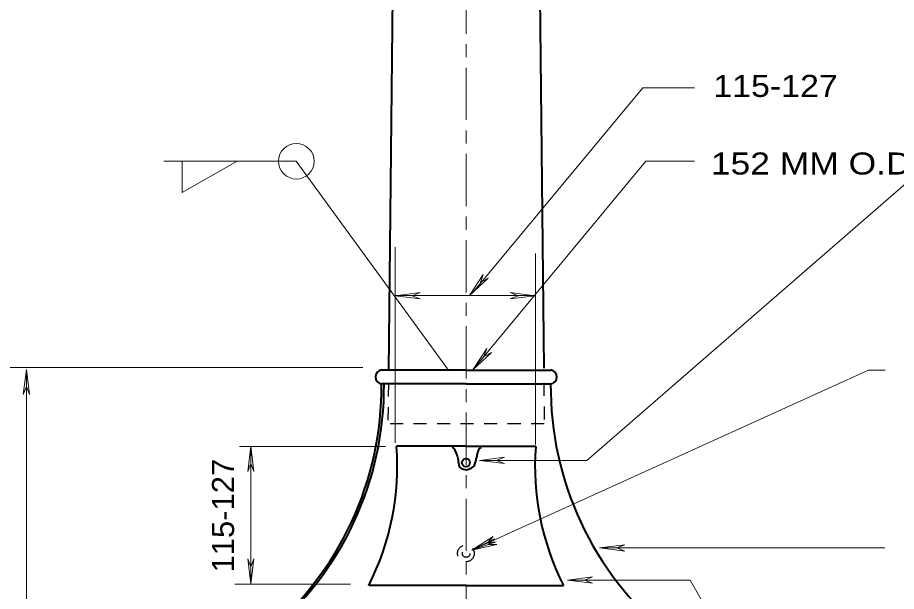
# Model space of a CAD drawing. Extents: x 312583 to 312854, y 144419 to 144597.
# Drawn here: x 312624.63 to 312654.89, y 144455.33 to 144475.1 of the extents above; entities that cross this region are included whole.
import ezdxf

# ---------------------------------------------------------------- set-up
doc = ezdxf.new("R2010")
doc.units = 0
doc.header["$LTSCALE"] = 0.3
doc.linetypes.add('LONG_DASH_SHORT_DASH', pattern=[9.9, 6, -1.2, 1.5, -1.2])
doc.linetypes.add('SHORT_DASHED', pattern=[2.7, 1.5, -1.2])
doc.layers.add('1', color=7, linetype='Continuous', lineweight=40)
doc.layers.add('2', color=7, linetype='Continuous', lineweight=13)

msp = doc.modelspace()

# ---------------------------------------------------------------- linework, layer by layer
at = {"layer": '1', "linetype": 'LONG_DASH_SHORT_DASH', "lineweight": 13}
msp.add_line((312640.0738, 144435.9326), (312640.0738, 144549.4913), dxfattribs=at)
at = {"layer": '1'}
for p, q in [((312638.2185, 144543.4576), (312637.4058, 144462.9576)), ((312641.9292, 144543.4576), (312642.7495, 144463.0189)), ((312640.0738, 144462.9576), (312637.1605, 144462.9576)), ((312640.0738, 144462.9576), (312637.1605, 144462.9576)), ((312640.0738, 144462.9576), (312637.1605, 144462.9576)), ((312640.0738, 144462.9576), (312637.1605, 144462.9576)), ((312640.0738, 144462.9576), (312637.1605, 144462.9576)), ((312640.0738, 144462.9576), (312637.1605, 144462.9576)), ((312640.0738, 144462.9576), (312637.1605, 144462.9576)), ((312640.0738, 144462.9576), (312637.1605, 144462.9576)), ((312640.0738, 144462.9576), (312642.9872, 144462.9576)), ((312640.0738, 144462.9576), (312642.9872, 144462.9576)), ((312640.0738, 144462.9576), (312642.9872, 144462.9576)), ((312640.0738, 144462.9576), (312642.9872, 144462.9576)), ((312640.0738, 144462.9576), (312642.9872, 144462.9576)), ((312640.0738, 144462.9576), (312642.9872, 144462.9576)), ((312640.0738, 144462.9576), (312642.9872, 144462.9576)), ((312640.0738, 144462.9576), (312642.9872, 144462.9576)), ((312640.0738, 144462.4823), (312637.1605, 144462.4823)), ((312640.0738, 144462.4823), (312637.1605, 144462.4823)), ((312640.0738, 144462.4823), (312637.1605, 144462.4823)), ((312640.0738, 144462.4823), (312637.1605, 144462.4823)), ((312640.0738, 144462.4823), (312637.1605, 144462.4823)), ((312640.0738, 144462.4823), (312637.1605, 144462.4823)), ((312640.0738, 144462.4823), (312637.1605, 144462.4823)), ((312640.0738, 144462.4823), (312637.1605, 144462.4823)), ((312640.0738, 144462.4823), (312642.9872, 144462.4823)), ((312640.0738, 144462.4823), (312642.9872, 144462.4823)), ((312640.0738, 144462.4823), (312642.9872, 144462.4823)), ((312640.0738, 144462.4823), (312642.9872, 144462.4823)), ((312640.0738, 144462.4823), (312642.9872, 144462.4823)), ((312640.0738, 144462.4823), (312642.9872, 144462.4823)), ((312640.0738, 144462.4823), (312642.9872, 144462.4823)), ((312640.0738, 144462.4823), (312642.9872, 144462.4823)), ((312640.0738, 144460.3279), (312637.6818, 144460.3279)), ((312640.0738, 144460.3279), (312637.6818, 144460.3279)), ((312640.0738, 144460.3279), (312637.6818, 144460.3279)), ((312640.0738, 144460.3279), (312637.6818, 144460.3279)), ((312640.0738, 144460.3279), (312637.6818, 144460.3279)), ((312640.0738, 144460.3279), (312637.6818, 144460.3279)), ((312640.0738, 144460.3279), (312637.6818, 144460.3279)), ((312640.0738, 144460.3279), (312637.6818, 144460.3279)), ((312640.0738, 144460.3279), (312642.4735, 144460.3279)), ((312640.0738, 144460.3279), (312642.4735, 144460.3279)), ((312640.0738, 144460.3279), (312642.4735, 144460.3279)), ((312640.0738, 144460.3279), (312642.4735, 144460.3279)), ((312640.0738, 144460.3279), (312642.4735, 144460.3279)), ((312640.0738, 144460.3279), (312642.4735, 144460.3279)), ((312640.0738, 144460.3279), (312642.4735, 144460.3279)), ((312640.0738, 144460.3279), (312642.4735, 144460.3279)), ((312640.0738, 144455.5363), (312636.7235, 144455.5363)), ((312640.0738, 144455.5363), (312636.7235, 144455.5363)), ((312640.0738, 144455.5363), (312636.7235, 144455.5363)), ((312640.0738, 144455.5363), (312636.7235, 144455.5363)), ((312640.0738, 144455.5363), (312636.7235, 144455.5363)), ((312640.0738, 144455.5363), (312636.7235, 144455.5363)), ((312640.0738, 144455.5363), (312636.7235, 144455.5363)), ((312640.0738, 144455.5363), (312636.7235, 144455.5363)), ((312640.0738, 144455.5363), (312643.4318, 144455.5363)), ((312640.0738, 144455.5363), (312643.4318, 144455.5363)), ((312640.0738, 144455.5363), (312643.4318, 144455.5363)), ((312640.0738, 144455.5363), (312643.4318, 144455.5363)), ((312640.0738, 144455.5363), (312643.4318, 144455.5363)), ((312640.0738, 144455.5363), (312643.4318, 144455.5363)), ((312640.0738, 144455.5363), (312643.4318, 144455.5363)), ((312640.0738, 144455.5363), (312643.4318, 144455.5363))]:
    msp.add_line(p, q, dxfattribs=at)
at = {"layer": '1', "linetype": 'SHORT_DASHED', "lineweight": 25}
for p, q in [((312637.3982, 144462.4899), (312637.3828, 144461.1023)), ((312642.7495, 144462.5129), (312642.7648, 144461.1023)), ((312642.7648, 144461.1023), (312637.3828, 144461.1023))]:
    msp.add_line(p, q, dxfattribs=at)
at = {"layer": '1'}
msp.add_circle((312640.0666, 144459.7649), 0.1386, dxfattribs=at)
at = {"layer": '1', "linetype": 'SHORT_DASHED', "lineweight": 25}
for centre, radius in [((312640.0671, 144456.6374), 0.2875), ((312640.0772, 144456.6297), 0.1279)]:
    msp.add_circle(centre, radius, dxfattribs=at)
at = {"layer": '1'}
for centre, radius, start, end in [((312637.1893, 144462.7199), 0.241, 96.16558, 263.83442), ((312637.1893, 144462.7199), 0.241, 96.16558, 263.83442), ((312637.1893, 144462.7199), 0.241, 96.16558, 263.83442), ((312637.1893, 144462.7199), 0.241, 96.16558, 263.83442), ((312637.1893, 144462.7199), 0.241, 96.16558, 263.83442), ((312637.1893, 144462.7199), 0.241, 96.16558, 263.83442), ((312637.1893, 144462.7199), 0.241, 96.16558, 263.83442), ((312637.1893, 144462.7199), 0.241, 96.16558, 263.83442), ((312642.9603, 144462.7199), 0.241, 276.16558, 83.83442), ((312642.9603, 144462.7199), 0.241, 276.16558, 83.83442), ((312642.9603, 144462.7199), 0.241, 276.16558, 83.83442), ((312642.9603, 144462.7199), 0.241, 276.16558, 83.83442), ((312642.9603, 144462.7199), 0.241, 276.16558, 83.83442), ((312642.9603, 144462.7199), 0.241, 276.16558, 83.83442), ((312642.9603, 144462.7199), 0.241, 276.16558, 83.83442), ((312642.9603, 144462.7199), 0.241, 276.16558, 83.83442), ((312626.0861, 144462.3949), 11.0776, 309.56623, 0.44182), ((312626.0861, 144462.3949), 11.0776, 309.56623, 0.44182), ((312626.0861, 144462.3949), 11.0776, 309.56623, 0.44182), ((312626.0861, 144462.3949), 11.0776, 309.56623, 0.44182), ((312626.0861, 144462.3949), 11.0776, 309.56623, 0.44182), ((312626.0861, 144462.3949), 11.0776, 309.56623, 0.44182), ((312626.0861, 144462.3949), 11.0776, 309.56623, 0.44182), ((312626.1714, 144462.3949), 11.0776, 309.56623, 0.44182), ((312654.0635, 144462.3949), 11.0776, 179.55818, 230.43377), ((312654.0635, 144462.3949), 11.0776, 179.55818, 230.43377), ((312654.0635, 144462.3949), 11.0776, 179.55818, 230.43377), ((312654.0635, 144462.3949), 11.0776, 179.55818, 230.43377), ((312654.0635, 144462.3949), 11.0776, 179.55818, 230.43377), ((312654.0635, 144462.3949), 11.0776, 179.55818, 230.43377), ((312654.0635, 144462.3949), 11.0776, 179.55818, 230.43377), ((312654.0635, 144462.3949), 11.0776, 179.55818, 230.43377), ((312628.609, 144459.6464), 9.0952, 333.10708, 4.27306), ((312628.609, 144459.6464), 9.0952, 333.10708, 4.27306), ((312628.609, 144459.6464), 9.0952, 333.10708, 4.27306), ((312628.609, 144459.6464), 9.0952, 333.10708, 4.27306), ((312628.609, 144459.6464), 9.0952, 333.10708, 4.27306), ((312628.609, 144459.6464), 9.0952, 333.10708, 4.27306), ((312628.609, 144459.6464), 9.0952, 333.10708, 4.27306), ((312628.609, 144459.6464), 9.0952, 333.10708, 4.27306), ((312651.5405, 144459.6464), 9.0952, 175.72694, 206.89292), ((312651.5405, 144459.6464), 9.0952, 175.72694, 206.89292), ((312651.5405, 144459.6464), 9.0952, 175.72694, 206.89292), ((312651.5405, 144459.6464), 9.0952, 175.72694, 206.89292), ((312651.5405, 144459.6464), 9.0952, 175.72694, 206.89292), ((312651.5405, 144459.6464), 9.0952, 175.72694, 206.89292), ((312651.5405, 144459.6464), 9.0952, 175.72694, 206.89292), ((312651.5405, 144459.6464), 9.0952, 175.72694, 206.89292)]:
    msp.add_arc(centre, radius, start, end, dxfattribs=at)
msp.add_spline([(312639.5985, 144460.3203), (312639.6752, 144460.2129), (312639.7288, 144460.0826), (312639.7748, 144459.9599), (312639.8055, 144459.8066), (312639.8592, 144459.6073), (312639.9818, 144459.5383), (312640.0892, 144459.5229), (312640.2195, 144459.5613), (312640.3422, 144459.6456), (312640.3958, 144459.7836), (312640.4342, 144459.9216), (312640.4648, 144460.0519), (312640.4955, 144460.1669), (312640.5338, 144460.2513), (312640.5875, 144460.2896)], degree=3, dxfattribs=at)
at = {"layer": '2'}
for p, q in [((312640.3115, 144465.6333), (312646.1612, 144472.6866)), ((312647.9398, 144472.6866), (312646.1612, 144472.6866)), ((312640.4188, 144463.0956), (312646.2685, 144470.1489)), ((312647.9398, 144470.1489), (312646.2685, 144470.1489)), ((312644.2292, 144459.8449), (312655.3053, 144469.4616)), ((312637.6282, 144467.1896), (312637.6282, 144460.4506)), ((312642.4658, 144466.9749), (312642.4658, 144460.3893)), ((312640.1965, 144465.5259), (312640.6642, 144466.2543)), ((312640.1965, 144465.5259), (312640.8328, 144466.1239)), ((312640.6642, 144466.2543), (312640.5722, 144465.9783)), ((312640.8328, 144466.1239), (312640.5722, 144465.9783)), ((312637.6282, 144465.5183), (312638.4945, 144465.6256)), ((312637.6282, 144465.5259), (312642.4122, 144465.5259)), ((312637.6282, 144465.5183), (312638.4945, 144465.4109)), ((312638.4945, 144465.6256), (312638.2185, 144465.5183)), ((312638.4945, 144465.4109), (312638.2185, 144465.5183)), ((312641.5918, 144465.6256), (312641.8678, 144465.5183)), ((312642.4582, 144465.5183), (312641.5918, 144465.6256)), ((312641.5918, 144465.4109), (312641.8678, 144465.5183)), ((312642.4582, 144465.5183), (312641.5918, 144465.4109)), ((312640.3115, 144462.9653), (312640.7868, 144463.7013)), ((312640.7868, 144463.7013), (312640.6872, 144463.4176)), ((312640.3115, 144462.9653), (312640.9478, 144463.5633)), ((312640.9478, 144463.5633), (312640.6872, 144463.4176)), ((312624.9307, 144462.9806), (312624.8233, 144462.1143)), ((312624.9307, 144451.6953), (312624.9307, 144462.9806)), ((312624.9307, 144462.9806), (312625.038, 144462.1143)), ((312640.2732, 144456.7476), (312653.9309, 144462.9562)), ((312654.5059, 144462.9562), (312653.9309, 144462.9562)), ((312624.8233, 144462.1143), (312624.9307, 144462.3903)), ((312625.038, 144462.1143), (312624.9307, 144462.3903)), ((312637.2985, 144460.3203), (312632.2692, 144460.3203)), ((312632.6602, 144460.3279), (312632.5528, 144459.4616)), ((312632.6602, 144460.3279), (312632.6602, 144455.5899)), ((312632.6602, 144460.3279), (312632.7675, 144459.4616)), ((312640.5338, 144459.8449), (312641.4002, 144459.9523)), ((312644.2292, 144459.8449), (312640.5338, 144459.8449)), ((312640.5338, 144459.8449), (312641.4002, 144459.7376)), ((312641.4002, 144459.9523), (312641.1242, 144459.8449)), ((312641.4002, 144459.7376), (312641.1242, 144459.8449)), ((312632.5528, 144459.4616), (312632.6602, 144459.7376)), ((312632.7675, 144459.4616), (312632.6602, 144459.7376)), ((312640.2732, 144456.7476), (312641.007, 144457.2229)), ((312640.2732, 144456.7476), (312641.0552, 144457.1386)), ((312640.2732, 144456.7476), (312641.1052, 144457.0333)), ((312641.007, 144457.2229), (312640.8072, 144457.0077)), ((312641.1052, 144457.0333), (312640.8072, 144457.0077)), ((312641.0552, 144457.1386), (312640.8328, 144456.9469)), ((312640.2732, 144456.7476), (312641.1318, 144456.9393)), ((312641.1318, 144456.9393), (312640.8328, 144456.9469)), ((312644.6738, 144456.8243), (312645.5402, 144456.9316)), ((312644.6738, 144456.8243), (312645.5402, 144456.7169)), ((312654.4994, 144456.8243), (312644.6738, 144456.8243)), ((312645.5402, 144456.9316), (312645.2642, 144456.8243)), ((312645.5402, 144456.7169), (312645.2642, 144456.8243)), ((312632.5528, 144456.4563), (312632.6602, 144456.1803)), ((312632.6602, 144455.5899), (312632.5528, 144456.4563)), ((312632.7675, 144456.4563), (312632.6602, 144456.1803)), ((312632.6602, 144455.5899), (312632.7675, 144456.4563)), ((312643.5622, 144455.7203), (312644.4285, 144455.8276)), ((312644.4285, 144455.8276), (312644.1525, 144455.7203)), ((312636.0948, 144455.5823), (312632.1082, 144455.5823)), ((312647.7865, 144455.7203), (312643.5622, 144455.7203)), ((312643.5622, 144455.7203), (312644.4285, 144455.6129)), ((312644.4285, 144455.6129), (312644.1525, 144455.7203)), ((312647.7865, 144455.7203), (312654.1728, 144444.6419))]:
    msp.add_line(p, q, dxfattribs=at)
for points in [[(312639.4682, 144462.9576), (312634.2242, 144470.1489), (312629.6625, 144470.1489)], [(312630.2988, 144470.1643), (312630.2988, 144469.0756), (312632.1925, 144470.1489)], [(312636.5165, 144463.0419), (312624.8632, 144463.0419), (312623.7925, 144463.0419)]]:
    msp.add_lwpolyline(points, dxfattribs=at)
msp.add_circle((312634.2261, 144470.1509), 0.6131, dxfattribs=at)

# ---------------------------------------------------------------- texts
for s, width, p in [('115-127 ', 1.15, (312648.5873, 144472.3675)), ('152 MM O.D.', 1.2, (312648.5036, 144469.6936))]:
    msp.add_text(s, height=0.76, dxfattribs=dict(at, width=width)).set_placement(p)
at = {"layer": '2', "width": 1.05}
msp.add_text('115-127', height=0.76, rotation=90, dxfattribs=at).set_placement((312632.0821, 144455.9811))

doc.saveas('drawing.dxf')
